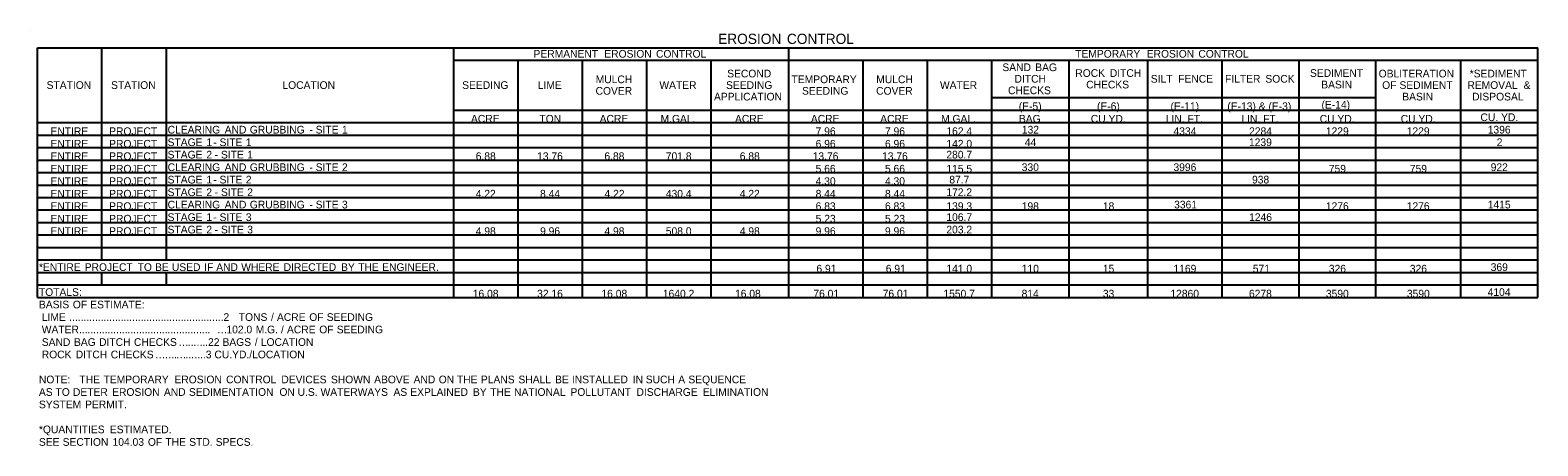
# Model space of a CAD drawing. Extents: x 977434 to 989596, y 1525697 to 1528336.
# Drawn here: x 980864 to 982040, y 1525697 to 1526021 of the extents above; entities that cross this region are included whole.
import ezdxf

# ---------------------------------------------------------------- set-up
doc = ezdxf.new("R2010")
doc.units = 0
doc.layers.add('Default', color=7, linetype='Continuous')
doc.layers.add('R_Border Prem', color=7, linetype='Continuous')

msp = doc.modelspace()

# ---------------------------------------------------------------- linework, layer by layer
at = {"layer": 'Default'}
for p, q in [((980869.9, 1526007.8), (982040.4, 1526007.8)), ((980869.9, 1525812.8), (980869.9, 1526007.8)), ((980869.9, 1525812.8), (980869.9, 1526007.8)), ((980920.1, 1525842.1), (980920.1, 1526007.8)), ((980970.3, 1525842.1), (980970.3, 1526007.8)), ((981194.6, 1525812.8), (981194.6, 1526007.8)), ((981455.9, 1525998.1), (981455.9, 1526007.8)), ((981455.9, 1525812.8), (981455.9, 1526007.8)), ((982040.4, 1525812.8), (982040.4, 1526007.8)), ((981194.6, 1525998.1), (982040.4, 1525998.1)), ((981244.8, 1525812.8), (981244.8, 1525998.1)), ((981295, 1525812.8), (981295, 1525998.1)), ((981345.2, 1525812.8), (981345.2, 1525998.1)), ((981395.4, 1525812.8), (981395.4, 1525998.1)), ((981513.9, 1525812.8), (981513.9, 1525998.1)), ((981564.1, 1525812.8), (981564.1, 1525998.1)), ((981614.3, 1525812.8), (981614.3, 1525998.1)), ((981674.8, 1525812.8), (981674.8, 1525998.1)), ((981736.2, 1525812.8), (981736.2, 1525998.1)), ((981794.2, 1525812.8), (981794.2, 1525998.1)), ((981854.2, 1525812.8), (981854.2, 1525998.1)), ((981914.1, 1525812.8), (981914.1, 1525998.1)), ((981980.4, 1525812.8), (981980.4, 1525998.1)), ((981614.3, 1525968.8), (981914.1, 1525968.8)), ((981794.2, 1525968.8), (981914.1, 1525968.8)), ((981194.6, 1525959.1), (982040.4, 1525959.1)), ((981244.8, 1525812.8), (981244.8, 1525959.1)), ((981295, 1525822.6), (981295, 1525959.1)), ((981345.2, 1525822.6), (981345.2, 1525959.1)), ((981395.4, 1525822.6), (981395.4, 1525959.1)), ((981455.9, 1525822.6), (981455.9, 1525959.1)), ((981513.9, 1525812.8), (981513.9, 1525959.1)), ((981564.1, 1525812.8), (981564.1, 1525959.1)), ((981614.3, 1525822.6), (981614.3, 1525959.1)), ((981674.8, 1525822.6), (981674.8, 1525959.1)), ((981736.2, 1525822.6), (981736.2, 1525959.1)), ((981794.2, 1525812.8), (981794.2, 1525959.1)), ((981854.2, 1525812.8), (981854.2, 1525959.1)), ((981914.1, 1525959.1), (982040.4, 1525959.1)), ((981914.1, 1525812.8), (981914.1, 1525959.1)), ((981980.4, 1525812.8), (981980.4, 1525959.1)), ((980869.9, 1525949.3), (982040.4, 1525949.3)), ((980920.1, 1525842.1), (980920.1, 1525949.3)), ((980970.3, 1525842.1), (980970.3, 1525949.3)), ((981194.6, 1525842.1), (981194.6, 1525949.3)), ((982040.4, 1525822.6), (982040.4, 1525949.3)), ((980869.9, 1525939.6), (982040.4, 1525939.6)), ((980869.9, 1525929.8), (982040.4, 1525929.8)), ((980869.9, 1525920.1), (982040.4, 1525920.1)), ((980869.9, 1525910.3), (982040.4, 1525910.3)), ((980869.9, 1525900.6), (982040.4, 1525900.6)), ((980869.9, 1525890.8), (982040.4, 1525890.8)), ((980869.9, 1525881.1), (982040.4, 1525881.1)), ((980869.9, 1525871.3), (982040.4, 1525871.3)), ((980869.9, 1525861.6), (982040.4, 1525861.6)), ((980869.9, 1525851.8), (982040.4, 1525851.8)), ((980869.9, 1525842.1), (982040.4, 1525842.1)), ((980869.9, 1525832.3), (982040.4, 1525832.3)), ((980920.1, 1525822.6), (980920.1, 1525832.3)), ((980920.1, 1525822.6), (980920.1, 1525832.3)), ((980970.3, 1525822.6), (980970.3, 1525832.3)), ((980970.3, 1525822.6), (980970.3, 1525832.3)), ((981194.6, 1525812.8), (981194.6, 1525832.3)), ((980869.9, 1525822.6), (981914.1, 1525822.6)), ((981244.8, 1525822.6), (981455.9, 1525822.6)), ((981455.9, 1525822.6), (981513.9, 1525822.6)), ((981513.9, 1525822.6), (981736.2, 1525822.6)), ((981736.2, 1525822.6), (981914.1, 1525822.6)), ((981914.1, 1525822.6), (982040.4, 1525822.6)), ((981980.4, 1525822.6), (982040.4, 1525822.6)), ((980869.9, 1525812.8), (982040.4, 1525812.8))]:
    msp.add_line(p, q, dxfattribs=at)
at = {"layer": 'R_Border Prem'}
msp.add_line((980864, 1526021.5), (980864, 1526021.5), dxfattribs=at)

# ---------------------------------------------------------------- texts
at = {"layer": 'Default'}
for s, height, p in [('EROSION', 8, (981400.8, 1526010.7)), (' CONTROL', 8, (981451.5, 1526010.7)), ('PERMANENT', 6, (981256.8, 1526000)), (' EROSION', 6, (981309.8, 1526000)), (' CONTROL', 6, (981350.1, 1526000)), ('TEMPORARY', 6, (981679.4, 1526000)), (' EROSION', 6, (981733, 1526000)), (' CONTROL', 6, (981773.3, 1526000)), ('SAND', 6, (981622.6, 1525989.5)), (' BAG', 6, (981646, 1525989.5)), ('STATION', 6, (980876.9, 1525975.6)), ('STATION', 6, (980927.2, 1525975.6)), ('LOCATION', 6, (981060.9, 1525975.6)), ('SEEDING', 6, (981201.1, 1525975.6)), ('LIME', 6, (981260.1, 1525975.6)), ('MULCH', 6, (981305.3, 1525980.1)), ('WATER', 6, (981355, 1525975.6)), ('SEEDING', 6, (981407, 1525975.6)), ('SECOND', 6, (981407.9, 1525984.6)), ('TEMPORARY', 6, (981458.1, 1525980.1)), ('MULCH', 6, (981524.2, 1525980.1)), ('WATER', 6, (981573.9, 1525975.6)), ('DITCH', 6, (981632.1, 1525980.5)), ('ROCK', 6, (981679.5, 1525985)), ('CHECKS', 6, (981688, 1525976)), (' DITCH', 6, (981704.2, 1525985)), ('SILT  FENCE ', 6, (981738.4, 1525980.5)), ('FILTER', 6, (981796.3, 1525980.5)), (' SOCK', 6, (981825.6, 1525980.5)), ('SEDIMENT', 6, (981862.6, 1525985)), ('BASIN', 6, (981871.4, 1525976)), ('OBLITERATION', 6, (981916.2, 1525984.6)), ('OF', 6, (981918.9, 1525975.6)), (' SEDIMENT', 6, (981930.2, 1525975.6)), ('REMOVAL', 6, (981985.4, 1525975.6)), ('*SEDIMENT', 6, (981987.2, 1525984.6)), (' &', 6, (982027.1, 1525975.6)), ('COVER', 6, (981305.2, 1525971.1)), ('APPLICATION', 6, (981397.6, 1525966.6)), ('SEEDING', 6, (981466.3, 1525971.1)), ('COVER', 6, (981524.1, 1525971.1)), ('CHECKS', 6, (981627, 1525971.5)), ('BASIN', 6, (981934.6, 1525966.6)), ('DISPOSAL', 6, (981989.1, 1525966.6)), ('(E-5)', 6, (981635.4, 1525959.1)), ('(E-6)', 6, (981696.4, 1525959.1)), ('(E-11)', 6, (981753.8, 1525959.1)), ('(E-13) & (E-3)', 6, (981798.1, 1525959.1)), ('(E-14)', 6, (981871.6, 1525960.3)), ('ENTIRE', 6, (980879.9, 1525939.6)), ('PROJECT', 6, (980925.7, 1525939.6)), ('CLEARING', 6, (980971.3, 1525940.8)), (' AND', 6, (981013.6, 1525940.8)), (' GRUBBING', 6, (981033.2, 1525940.8)), (' SITE', 6, (981084.6, 1525940.8)), (' 1', 6, (981105.1, 1525940.8)), ('ACRE', 6, (981208, 1525949.3)), ('TON', 6, (981261.4, 1525949.3)), ('ACRE', 6, (981308.4, 1525949.3)), ('M.GAL.', 6, (981355.9, 1525949.3)), ('ACRE', 6, (981414, 1525949.3)), ('ACRE', 6, (981473.2, 1525949.3)), ('7.96', 6, (981476.9, 1525939.6)), ('ACRE', 6, (981527.3, 1525949.3)), ('7.96', 6, (981531, 1525939.6)), ('M.GAL.', 6, (981574.8, 1525949.3)), ('162.4', 6, (981578.9, 1525939.6)), ('BAG', 6, (981635.5, 1525949.3)), ('132', 6, (981637.8, 1525940.8)), ('CU.YD.', 6, (981691.6, 1525949.3)), ('LIN. FT.', 6, (981750.1, 1525949.3)), ('4334', 6, (981756.1, 1525939.6)), ('LIN. FT.', 6, (981809.1, 1525949.3)), ('2284', 6, (981815.1, 1525939.6)), ('CU.YD.', 6, (981870.2, 1525949.3)), ('1229', 6, (981875, 1525939.6)), ('CU.YD.', 6, (981933.4, 1525949.3)), ('1229', 6, (981938.1, 1525939.6)), ('CU.', 6, (981995.6, 1525950.5)), ('1396', 6, (982001.3, 1525940.8)), (' YD.', 6, (982009.5, 1525950.5)), ('ENTIRE', 6, (980879.9, 1525929.8)), ('PROJECT', 6, (980925.7, 1525929.8)), ('STAGE', 6, (980971.3, 1525931)), (' 1', 6, (980999.3, 1525931)), (' -', 6, (981004.7, 1525931)), (' SITE', 6, (981009.6, 1525931)), (' 1', 6, (981030.1, 1525931)), (' -', 6, (981079.7, 1525940.8)), ('6.96', 6, (981476.9, 1525929.8)), ('6.96', 6, (981531, 1525929.8)), ('142.0', 6, (981578.9, 1525929.8)), ('44', 6, (981640.1, 1525931)), ('1239', 6, (981815, 1525931)), ('2', 6, (982008.3, 1525931)), ('ENTIRE', 6, (980879.9, 1525920.1)), ('PROJECT', 6, (980925.7, 1525920.1)), ('STAGE', 6, (980971.3, 1525921.3)), (' 2', 6, (980999.3, 1525921.3)), (' -', 6, (981005.8, 1525921.3)), (' SITE', 6, (981010.7, 1525921.3)), (' 1', 6, (981031.2, 1525921.3)), ('6.88', 6, (981211.7, 1525920.1)), ('13.76', 6, (981259.6, 1525920.1)), ('6.88', 6, (981312.1, 1525920.1)), ('701.8', 6, (981360, 1525920.1)), ('6.88', 6, (981417.7, 1525920.1)), ('13.76', 6, (981474.6, 1525920.1)), ('13.76', 6, (981528.7, 1525920.1)), ('280.7', 6, (981578.9, 1525921.3)), ('ENTIRE', 6, (980879.9, 1525910.3)), ('PROJECT', 6, (980925.7, 1525910.3)), ('CLEARING', 6, (980971.3, 1525911.5)), (' AND', 6, (981013.6, 1525911.5)), (' GRUBBING', 6, (981033.2, 1525911.5)), (' -', 6, (981079.7, 1525911.5)), (' SITE', 6, (981084.6, 1525911.5)), (' 2', 6, (981105.1, 1525911.5)), ('5.66', 6, (981476.9, 1525910.3)), ('5.66', 6, (981531, 1525910.3)), ('115.5', 6, (981578.9, 1525910.3)), ('330', 6, (981637.7, 1525911.5)), ('3996', 6, (981756.1, 1525911.5)), ('759', 6, (981877.3, 1525910.3)), ('759', 6, (981940.5, 1525910.3)), ('922', 6, (982003.6, 1525911.5)), ('ENTIRE', 6, (980879.9, 1525900.6)), ('PROJECT', 6, (980925.7, 1525900.6)), ('STAGE', 6, (980971.3, 1525901.8)), ('STAGE', 6, (980971.3, 1525892)), (' 2', 6, (980999.3, 1525892)), (' 1', 6, (980999.3, 1525901.8)), (' -', 6, (981004.7, 1525901.8)), (' SITE', 6, (981009.6, 1525901.8)), (' SITE', 6, (981010.7, 1525892)), (' 2', 6, (981030.1, 1525901.8)), (' 2', 6, (981031.2, 1525892)), ('4.30', 6, (981476.9, 1525900.6)), ('4.30', 6, (981531, 1525900.6)), ('172.2', 6, (981578.9, 1525892)), ('87.7', 6, (981581.2, 1525901.8)), ('938', 6, (981817.4, 1525901.8)), ('ENTIRE', 6, (980879.9, 1525890.8)), ('ENTIRE', 6, (980879.9, 1525881.1)), ('PROJECT', 6, (980925.7, 1525890.8)), ('PROJECT', 6, (980925.7, 1525881.1)), ('CLEARING', 6, (980971.3, 1525882.3)), (' -', 6, (981005.8, 1525892)), (' AND', 6, (981013.6, 1525882.3)), (' GRUBBING', 6, (981033.2, 1525882.3)), (' SITE', 6, (981084.6, 1525882.3)), (' 3', 6, (981105.1, 1525882.3)), ('4.22', 6, (981211.7, 1525890.8)), ('8.44', 6, (981261.9, 1525890.8)), ('4.22', 6, (981312.2, 1525890.8)), ('430.4', 6, (981360, 1525890.8)), ('4.22', 6, (981417.7, 1525890.8)), ('8.44', 6, (981476.9, 1525890.8)), ('6.83', 6, (981476.9, 1525881.1)), ('8.44', 6, (981531, 1525890.8)), ('6.83', 6, (981531, 1525881.1)), ('139.3', 6, (981578.9, 1525881.1)), ('198', 6, (981637.7, 1525881.1)), ('18', 6, (981701, 1525881.1)), ('3361', 6, (981756.6, 1525882.3)), ('1276', 6, (981875, 1525881.1)), ('1276', 6, (981938.1, 1525881.1)), ('1415', 6, (982001.3, 1525882.3)), ('ENTIRE', 6, (980879.9, 1525871.3)), ('PROJECT', 6, (980925.7, 1525871.3)), ('STAGE', 6, (980971.3, 1525872.5)), (' 1', 6, (980999.3, 1525872.5)), (' -', 6, (981004.7, 1525872.5)), (' SITE', 6, (981009.6, 1525872.5)), (' 3', 6, (981030.1, 1525872.5)), (' -', 6, (981079.7, 1525882.3)), ('5.23', 6, (981476.9, 1525871.3)), ('5.23', 6, (981531, 1525871.3)), ('106.7', 6, (981578.9, 1525872.5)), ('1246', 6, (981815.1, 1525872.5)), ('ENTIRE', 6, (980879.9, 1525861.6)), ('PROJECT', 6, (980925.7, 1525861.6)), ('STAGE', 6, (980971.3, 1525862.8)), (' 2', 6, (980999.3, 1525862.8)), (' -', 6, (981005.8, 1525862.8)), (' SITE', 6, (981010.7, 1525862.8)), (' 3', 6, (981031.2, 1525862.8)), ('4.98', 6, (981211.7, 1525861.6)), ('9.96', 6, (981261.9, 1525861.6)), ('4.98', 6, (981312.1, 1525861.6)), ('508.0', 6, (981360, 1525861.6)), ('4.98', 6, (981417.7, 1525861.6)), ('9.96', 6, (981476.9, 1525861.6)), ('9.96', 6, (981531, 1525861.6)), ('203.2', 6, (981578.9, 1525862.8)), ('*ENTIRE', 6, (980870.9, 1525833.5)), (' PROJECT', 6, (980904.4, 1525833.5)), (' TO', 6, (980945.7, 1525833.5)), (' BE', 6, (980959.3, 1525833.5)), (' USED', 6, (980972.4, 1525833.5)), (' IF', 6, (980997.6, 1525833.5)), (' AND', 6, (981007, 1525833.5)), (' WHERE', 6, (981026.5, 1525833.5)), (' DIRECTED', 6, (981059.6, 1525833.5)), (' BY', 6, (981104.4, 1525833.5)), (' THE', 6, (981117.8, 1525833.5)), (' ENGINEER.', 6, (981136.5, 1525833.5)), ('369', 6, (982003.6, 1525833.5)), ('6.91', 6, (981477.5, 1525832.3)), ('6.91', 6, (981531.6, 1525832.3)), ('141.0', 6, (981578.9, 1525832.3)), ('110', 6, (981637.7, 1525832.3)), ('15', 6, (981701, 1525832.3)), ('1169', 6, (981756.1, 1525832.3)), ('571', 6, (981818, 1525832.3)), ('326', 6, (981877.3, 1525832.3)), ('326', 6, (981940.5, 1525832.3)), ('TOTALS:', 6, (980870.9, 1525814)), ('16.08', 6, (981209.4, 1525812.8)), ('32.16', 6, (981259.6, 1525812.8)), ('16.08', 6, (981309.8, 1525812.8)), ('1640.2', 6, (981357.7, 1525812.8)), ('16.08 ', 6, (981414, 1525812.8)), ('76.01', 6, (981475.1, 1525812.8)), ('76.01', 6, (981529.2, 1525812.8)), ('1550.7', 6, (981576.6, 1525812.8)), ('814', 6, (981637.6, 1525812.8)), ('33', 6, (981701, 1525812.8)), ('12860', 6, (981753.7, 1525812.8)), ('6278', 6, (981815, 1525812.8)), ('3590', 6, (981875, 1525812.8)), ('3590', 6, (981938.2, 1525812.8)), ('4104', 6, (982001.2, 1525814)), ('BASIS', 6, (980870.9, 1525804.3)), (' OF', 6, (980895.1, 1525804.3)), (' ESTIMATE:', 6, (980908.7, 1525804.3)), (' LIME', 6, (980870.9, 1525794.5)), (' ......................................................2', 6, (980892.3, 1525794.5)), (' TONS', 6, (981024.6, 1525794.5)), (' /', 6, (981049.7, 1525794.5)), (' ACRE', 6, (981054.4, 1525794.5)), (' OF', 6, (981079.6, 1525794.5)), (' SEEDING', 6, (981093.2, 1525794.5)), (' WATER..............................................', 6, (980870.9, 1525784.8)), (' SAND', 6, (980870.9, 1525775)), (' BAG', 6, (980896, 1525775)), (' DITCH', 6, (980915.6, 1525775)), (' CHECKS', 6, (980942.8, 1525775)), ('..22', 6, (980998.4, 1525775)), ('…', 6, (981009.8, 1525784.8)), (' BAGS', 6, (981011.9, 1525775)), ('102.0', 6, (981017.2, 1525784.8)), (' /', 6, (981037.1, 1525775)), (' M.G.', 6, (981037.8, 1525784.8)), (' LOCATION', 6, (981041.8, 1525775)), (' /', 6, (981057.5, 1525784.8)), (' ACRE', 6, (981062.2, 1525784.8)), (' OF', 6, (981087.4, 1525784.8)), (' SEEDING', 6, (981101, 1525784.8)), (' ROCK', 6, (980870.9, 1525765.3)), (' DITCH', 6, (980897.4, 1525765.3)), (' CHECKS', 6, (980924.7, 1525765.3)), ('…', 6, (980979.7, 1525775)), ('..', 6, (980987.1, 1525775)), ('…', 6, (980991, 1525775)), ('..3', 6, (980996.6, 1525765.3)), (' CU.YD./LOCATION', 6, (981005.6, 1525765.3)), ('…', 6, (980961.5, 1525765.3)), ('…', 6, (980968.9, 1525765.3)), ('.', 6, (980976.3, 1525765.3)), ('…', 6, (980977.9, 1525765.3)), ('..', 6, (980985.3, 1525765.3)), ('…', 6, (980989.2, 1525765.3)), ('NOTE:', 6, (980870.9, 1525745.8)), ('   THE', 6, (980895.8, 1525745.8)), (' TEMPORARY', 6, (980919.1, 1525745.8)), (' EROSION', 6, (980974.4, 1525745.8)), (' CONTROL', 6, (981014.7, 1525745.8)), (' DEVICES', 6, (981057.8, 1525745.8)), (' SHOWN', 6, (981096.5, 1525745.8)), (' ABOVE', 6, (981130.2, 1525745.8)), (' AND', 6, (981161, 1525745.8)), (' ON', 6, (981180.6, 1525745.8)), (' THE', 6, (981194.8, 1525745.8)), (' PLANS', 6, (981213.5, 1525745.8)), (' SHALL', 6, (981242.8, 1525745.8)), (' BE', 6, (981271.4, 1525745.8)), (' INSTALLED', 6, (981284.5, 1525745.8)), (' IN', 6, (981332, 1525745.8)), (' SUCH', 6, (981342.1, 1525745.8)), (' A', 6, (981367.5, 1525745.8)), (' SEQUENCE', 6, (981375.4, 1525745.8)), ('AS', 6, (980870.9, 1525736)), (' TO', 6, (980881.6, 1525736)), (' DETER', 6, (980895.2, 1525736)), (' EROSION', 6, (980925.8, 1525736)), (' AND', 6, (980966.2, 1525736)), (' SEDIMENTATION', 6, (980985.7, 1525736)), (' ON', 6, (981056.3, 1525736)), (' U.S.', 6, (981070.5, 1525736)), (' WATERWAYS', 6, (981088.4, 1525736)), (' AS', 6, (981145.3, 1525736)), (' EXPLAINED', 6, (981158.4, 1525736)), (' BY', 6, (981207.3, 1525736)), (' THE', 6, (981220.8, 1525736)), (' NATIONAL', 6, (981239.4, 1525736)), (' POLLUTANT', 6, (981283.4, 1525736)), (' DISCHARGE', 6, (981334.9, 1525736)), (' ELIMINATION', 6, (981386.6, 1525736)), ('SYSTEM', 6, (980870.9, 1525726.3)), (' PERMIT.', 6, (980904.7, 1525726.3)), ('*QUANTITIES', 6, (980870.9, 1525706.8)), (' ESTIMATED.', 6, (980924, 1525706.8)), ('SEE', 6, (980870.9, 1525697)), (' SECTION', 6, (980887.2, 1525697)), (' 104.03', 6, (980926.1, 1525697)), (' OF', 6, (980953.7, 1525697)), (' THE', 6, (980967.3, 1525697)), (' STD.', 6, (980985.9, 1525697)), (' SPECS.', 6, (981006.6, 1525697))]:
    msp.add_text(s, height=height, dxfattribs=at).set_placement(p)

doc.saveas('drawing.dxf')
